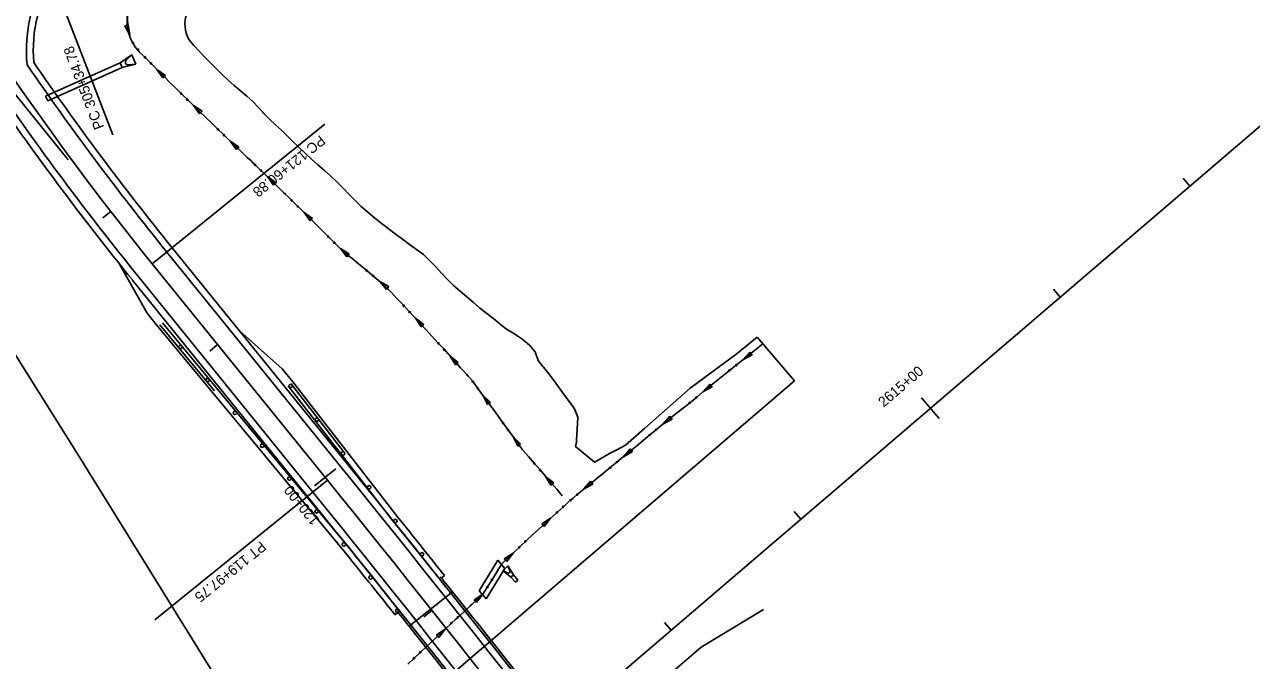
# Model space of a CAD drawing. Extents: x 916431 to 921570, y 1763982 to 1768032.
# Drawn here: x 918752 to 919470, y 1765157 to 1765530 of the extents above; entities that cross this region are included whole.
import ezdxf

# ---------------------------------------------------------------- set-up
doc = ezdxf.new("R2010")
doc.units = 0
for name, color, linetype in [('43', 7, 'Continuous'), ('B-Super-Deck', 7, 'Continuous'), ('R_Conc Ditch Paving', 7, 'Continuous'), ('R_Drainage', 7, 'Continuous'), ('R_Guardrail', 7, 'Continuous'), ('R_Horz Alg', 7, 'Continuous'), ('R_Horz Alg Annot', 7, 'Continuous'), ('R_Horz Alg Stationing', 7, 'Continuous'), ('R_Proposed Const Limits', 7, 'Continuous'), ('R_Proposed Road', 7, 'Continuous'), ('R_Shld', 7, 'Continuous'), ('R_Special Ditch', 7, 'Continuous')]:
    doc.layers.add(name, color=color, linetype=linetype)

# ---------------------------------------------------------------- blocks, each defined once
blk = doc.blocks.new('36F_PL')
at = {"layer": '43'}
for p, q in [((0, 0), (-0.15, -0.815)), ((0, 0), (0.3, 0)), ((0.45, -0.815), (0.3, 0)), ((-0.007, -0.402), (-0.15, -0.815)), ((0.308, -0.402), (0.45, -0.815)), ((-0.15, -0.815), (0.45, -0.815))]:
    blk.add_line(p, q, dxfattribs=at)
blk.add_arc((0.15, -0.456), 0.167, 19.04262, 160.95738, dxfattribs=at)
blk = doc.blocks.new('24F_PL')
at = {"layer": '43'}
for p, q in [((0, 0), (-0.1, -0.612)), ((0, 0), (0.2, 0)), ((0.2, 0), (0.3, -0.612)), ((-0.1, -0.612), (-0.011, -0.332)), ((-0.1, -0.612), (0.3, -0.612)), ((0.3, -0.612), (0.211, -0.332))]:
    blk.add_line(p, q, dxfattribs=at)
blk.add_arc((0.1, -0.367), 0.117, 17.52992, 162.47008, dxfattribs=at)

msp = doc.modelspace()

# ---------------------------------------------------------------- linework, layer by layer
at = {"layer": 'B-Super-Deck'}
for p, q in [((918995.36, 1765206.09), (918994.38, 1765205.31)), ((919002.21, 1765197.49), (918976.77, 1765177.26)), ((918969.92, 1765185.87), (918970.9, 1765186.65))]:
    msp.add_line(p, q, dxfattribs=at)
for radius, start, end in [(11474.16, 38.488592, 38.548508), (11475.41, 38.488592, 38.548507), (11474.16, 37.482766, 38.493585), (11475.41, 37.482766, 38.493585), (11442.91, 38.488593, 38.548678), (11444.16, 38.488593, 38.548677), (11442.91, 37.482752, 38.493599), (11444.16, 37.482752, 38.493599)]:
    msp.add_arc((910020.66, 1758054.88), radius, start, end, dxfattribs=at)
at = {"layer": 'R_Conc Ditch Paving'}
for p, q in [((919017.78, 1765198.07), (919028.8, 1765215.95)), ((919032.92, 1765211.18), (919028.8, 1765215.95)), ((919021.88, 1765193.28), (919032.92, 1765211.18)), ((919017.78, 1765198.07), (919021.88, 1765193.28))]:
    msp.add_line(p, q, dxfattribs=at)
at = {"layer": 'R_Drainage'}
for p, q in [((918807.55, 1765507.31), (918763.93, 1765487.87)), ((918808.77, 1765504.57), (918765.15, 1765485.13)), ((918763.93, 1765487.87), (918765.15, 1765485.13)), ((919036.4, 1765206.04), (919037.91, 1765207.35)), ((919036.4, 1765206.04), (919039.02, 1765203.02)), ((919037.91, 1765207.35), (919040.53, 1765204.32)), ((919039.02, 1765203.02), (919040.53, 1765204.32))]:
    msp.add_line(p, q, dxfattribs=at)
at = {"layer": 'R_Guardrail'}
for p, q in [((918862.8, 1765315.27), (918830.92, 1765353.79)), ((918944, 1765220.27), (918832.46, 1765355.07)), ((918967.37, 1765239.08), (918906.05, 1765318.17)), ((918938.27, 1765279.88), (918907.63, 1765319.4))]:
    msp.add_line(p, q, dxfattribs=at)
for points in [[(918970.66, 1765186.93), (918944, 1765220.27), (918832.46, 1765355.07)], [(918906.66, 1765317.38), (918967.37, 1765239.08), (918994.73, 1765204.87)]]:
    msp.add_lwpolyline(points, dxfattribs=at)
for centre in [(918842.94, 1765340.83), (918858.88, 1765321.57), (918907.45, 1765317.99), (918874.82, 1765302.31), (918922.77, 1765298.24), (918890.75, 1765283.05), (918938.09, 1765278.48), (918906.69, 1765263.79), (918953.41, 1765258.72), (918922.63, 1765244.53), (918968.73, 1765238.98), (918938.57, 1765225.27), (918984.34, 1765219.46), (918954.27, 1765205.83), (918969.88, 1765186.31)]:
    msp.add_circle(centre, 1, dxfattribs=at)
for radius, start, end in [(11474.16, 38.545676, 38.764426), (11444.16, 38.545526, 38.764276)]:
    msp.add_arc((910020.66, 1758054.88), radius, start, end, dxfattribs=at)
at = {"layer": 'R_Horz Alg'}
for p, q in [((918522.67, 1764654.46), (919661.81, 1765630.35)), ((918929, 1765262.78), (918826.39, 1765389.59))]:
    msp.add_line(p, q, dxfattribs=at)
for centre, radius, start, end in [((920196.91, 1766498.5), 1762.95, 202.25028, 218.97694), ((910020.66, 1758054.88), 11459.16, 34.999167, 38.976944)]:
    msp.add_arc(centre, radius, start, end, dxfattribs=at)
at = {"layer": 'R_Horz Alg Annot'}
msp.add_line((918663.37, 1765591.08), (918777.08, 1765450.54), dxfattribs=at)
for points in [[(918764.29, 1765566.55), (918803.28, 1765465.17)], [(918826.39, 1765389.59), (918927.45, 1765471.37)], [(918929, 1765262.78), (918827.94, 1765181.01)]]:
    msp.add_lwpolyline(points, dxfattribs=at)
at = {"layer": 'R_Horz Alg Stationing'}
for points in [[(919430.08, 1765439.73), (919433.98, 1765435.17)], [(918797.38, 1765416.61), (918802.13, 1765420.28)], [(919354.13, 1765374.67), (919358.04, 1765370.11)], [(918860.02, 1765338.49), (918864.69, 1765342.27)], [(919276.89, 1765311.13), (919287.3, 1765298.98)], [(918921.37, 1765259.49), (918933.81, 1765269.56)], [(919202.25, 1765244.55), (919206.15, 1765239.99)], [(918985.47, 1765182.79), (918990.16, 1765186.53)], [(919126.31, 1765179.49), (919130.21, 1765174.94)]]:
    msp.add_lwpolyline(points, dxfattribs=at)
at = {"layer": 'R_Proposed Const Limits'}
for points in [[(919074.23, 1765282.5), (919074.88, 1765285.18), (919074.93, 1765286.25), (919075.55, 1765299.36), (919075.57, 1765299.68), (919073.64, 1765304.62), (919070.66, 1765308.72), (919067.69, 1765312.82), (919064.71, 1765316.92), (919061.77, 1765321.05), (919058.73, 1765325.1), (919055.55, 1765329.03), (919055.19, 1765329.48), (919052.36, 1765332.96), (919050.67, 1765338.1), (919047.25, 1765341.85), (919043.59, 1765345.03), (919043.37, 1765345.22), (919040.51, 1765347.2), (919039.02, 1765348.21), (919036.5, 1765349.76), (919034.4, 1765350.95), (919030.31, 1765354.07), (919030.14, 1765354.22), (919026.37, 1765357.32), (919025.66, 1765357.87), (919022.31, 1765360.47), (919018.26, 1765363.62), (919014.43, 1765366.95), (919010.59, 1765370.28), (919006.75, 1765373.6), (919002.9, 1765376.92), (918999.29, 1765380.43), (918995.87, 1765384.09), (918992.45, 1765387.75), (918988.96, 1765391.37), (918985.38, 1765394.9), (918985.19, 1765395.07), (918981.22, 1765397.96), (918977.03, 1765401), (918972.85, 1765404.06), (918968.74, 1765407.17), (918964.62, 1765410.26), (918963.35, 1765411.2), (918960.47, 1765413.34), (918956.47, 1765416.53), (918952.65, 1765419.87), (918948.74, 1765423.14), (918945.17, 1765426.68), (918941.68, 1765430.29), (918938.21, 1765433.91), (918934.74, 1765437.54), (918931.04, 1765440.98), (918927.23, 1765444.32), (918923.35, 1765447.62), (918919.59, 1765451.01), (918915.86, 1765454.42), (918912.24, 1765457.92), (918908.81, 1765461.25), (918905.42, 1765464.55), (918903.95, 1765465.98), (918902.03, 1765467.84), (918898.6, 1765471.12), (918895.1, 1765474.34), (918891.79, 1765477.71), (918891.15, 1765478.45), (918888.69, 1765481.25), (918885.38, 1765484.64), (918881.75, 1765487.78), (918878.11, 1765490.91), (918874.46, 1765494.06), (918870.82, 1765497.21), (918867.41, 1765500.54), (918864.03, 1765503.9), (918860.64, 1765507.26), (918857.26, 1765510.63), (918853.97, 1765514.07), (918850.81, 1765517.61), (918847.82, 1765520.98)], [(918663.54, 1765493.36), (918697.72, 1765422.89), (918728.86, 1765363.64), (918783.6, 1765276.66), (918878.88, 1765122.86)], [(919180.63, 1765346.64), (919168.18, 1765336.52), (919154.83, 1765326.62), (919141.48, 1765316.71), (919128.21, 1765305.06), (919114.94, 1765293.41), (919103.47, 1765283.31)], [(919180.63, 1765346.64), (919202.49, 1765321.13)], [(919074.23, 1765282.5), (919085.37, 1765273.38), (919089.8, 1765275.9), (919094.26, 1765278.38), (919098.76, 1765280.82), (919103.47, 1765283.31)]]:
    msp.add_lwpolyline(points, dxfattribs=at)
msp.add_arc((918864.61, 1765529.99), 19.05, 112.67795, 208.20547, dxfattribs=at)
at = {"layer": 'R_Proposed Road'}
for p, q in [((918834.94, 1765396.51), (918937.55, 1765269.7)), ((918817.84, 1765382.68), (918920.45, 1765255.86))]:
    msp.add_line(p, q, dxfattribs=at)
for centre, radius, start, end in [((918837.71, 1765514.58), 85, 108.70584, 185.72161), ((920196.91, 1766498.5), 1751.95, 214.50329, 218.97694), ((920196.91, 1766498.5), 1773.95, 214.37448, 218.97694), ((910020.66, 1758054.88), 11470.16, 34.999167, 38.976944), ((910020.66, 1758054.88), 11448.16, 35.073221, 38.976944)]:
    msp.add_arc(centre, radius, start, end, dxfattribs=at)
at = {"layer": 'R_Shld'}
for p, q in [((918838.05, 1765399.03), (918940.66, 1765272.22)), ((918823.45, 1765360.64), (918806.94, 1765389.86)), ((918814.73, 1765380.16), (918917.34, 1765253.35)), ((918829.74, 1765352.87), (918824.04, 1765359.91)), ((918941.27, 1765218.08), (918829.74, 1765352.87)), ((918902.48, 1765328.15), (918877.45, 1765350.34)), ((918908.77, 1765320.37), (918902.48, 1765328.15)), ((919202.49, 1765321.13), (918784.8, 1764963.3)), ((918970.1, 1765241.27), (918908.77, 1765320.37)), ((918997.47, 1765207.05), (918995.71, 1765205.65)), ((919184.34, 1765187.07), (919147.89, 1765165.06)), ((918968.55, 1765183.97), (918970.31, 1765185.37)), ((919064.35, 1765093.5), (919147.89, 1765165.06))]:
    msp.add_line(p, q, dxfattribs=at)
for centre, radius, start, end in [((918837.71, 1765514.58), 81, 108.70584, 185.00335), ((920196.91, 1766498.5), 1747.95, 214.53735, 218.97694), ((920196.91, 1766498.5), 1777.95, 214.37448, 218.97694), ((920324.7, 1766574.12), 1930.36, 218.9491, 218.97694), ((910020.66, 1758054.88), 11474.16, 34.999167, 38.976944), ((910020.66, 1758054.88), 11444.16, 35.078536, 38.976944), ((910020.66, 1758054.88), 11477.66, 38.545676, 38.764426), ((910020.66, 1758054.88), 11440.66, 38.545526, 38.764276)]:
    msp.add_arc(centre, radius, start, end, dxfattribs=at)
at = {"layer": 'R_Special Ditch'}
for p, q in [((918812.31, 1765529.65), (918810.31, 1765528.96)), ((918810.31, 1765528.96), (918813.25, 1765523.63)), ((918813.25, 1765523.63), (918812.31, 1765529.65)), ((918829.16, 1765503.51), (918832.65, 1765498.52)), ((918834.15, 1765500.01), (918829.16, 1765503.51)), ((918832.65, 1765498.52), (918834.15, 1765500.01)), ((918850.5, 1765482.37), (918854.06, 1765477.43)), ((918855.54, 1765478.95), (918850.5, 1765482.37)), ((918854.06, 1765477.43), (918855.54, 1765478.95)), ((918872.1, 1765461.5), (918875.69, 1765456.58)), ((918877.16, 1765458.1), (918872.1, 1765461.5)), ((918875.69, 1765456.58), (918877.16, 1765458.1)), ((918893.79, 1765440.72), (918897.36, 1765435.78)), ((918898.84, 1765437.3), (918893.79, 1765440.72)), ((918897.36, 1765435.78), (918898.84, 1765437.3)), ((918915.26, 1765419.71), (918918.78, 1765414.74)), ((918920.27, 1765416.24), (918915.26, 1765419.71)), ((918918.78, 1765414.74), (918920.27, 1765416.24)), ((918936.58, 1765398.55), (918940.37, 1765393.79)), ((918941.77, 1765395.37), (918936.58, 1765398.55)), ((918940.37, 1765393.79), (918941.77, 1765395.37)), ((918959.61, 1765379.27), (918963.52, 1765374.6)), ((918964.88, 1765376.22), (918959.61, 1765379.27)), ((918963.52, 1765374.6), (918964.88, 1765376.22)), ((918980.52, 1765357.75), (918983.82, 1765352.62)), ((918985.37, 1765354.06), (918980.52, 1765357.75)), ((918983.82, 1765352.62), (918985.37, 1765354.06)), ((919176.3, 1765337.92), (919172.29, 1765333.33)), ((919177.62, 1765336.27), (919176.3, 1765337.92)), ((919000.8, 1765335.59), (919004.04, 1765330.43)), ((919005.61, 1765331.85), (919000.8, 1765335.59)), ((919004.04, 1765330.43), (919005.61, 1765331.85)), ((919172.29, 1765333.33), (919177.62, 1765336.27)), ((919152.86, 1765319.12), (919148.88, 1765314.51)), ((919148.88, 1765314.51), (919154.2, 1765317.48)), ((919154.2, 1765317.48), (919152.86, 1765319.12)), ((919020.05, 1765312.57), (919022.74, 1765307.1)), ((919024.45, 1765308.35), (919020.05, 1765312.57)), ((919022.74, 1765307.1), (919024.45, 1765308.35)), ((919129.46, 1765300.31), (919125.44, 1765295.73)), ((919125.44, 1765295.73), (919130.78, 1765298.65)), ((919130.78, 1765298.65), (919129.46, 1765300.31)), ((919037.72, 1765288.28), (919040.4, 1765282.81)), ((919042.11, 1765284.05), (919037.72, 1765288.28)), ((919040.4, 1765282.81), (919042.11, 1765284.05)), ((919106.28, 1765281.19), (919102.3, 1765276.58)), ((919107.61, 1765279.55), (919106.28, 1765281.19)), ((919102.3, 1765276.58), (919107.61, 1765279.55)), ((919056.77, 1765265.08), (919059.87, 1765259.84)), ((919061.48, 1765261.22), (919056.77, 1765265.08)), ((919059.87, 1765259.84), (919061.48, 1765261.22)), ((919083.02, 1765262.18), (919079.03, 1765257.58)), ((919079.03, 1765257.58), (919084.36, 1765260.54)), ((919084.36, 1765260.54), (919083.02, 1765262.18)), ((919059.66, 1765240.5), (919054.51, 1765237.23)), ((919055.94, 1765235.67), (919059.66, 1765240.5)), ((919054.51, 1765237.23), (919055.94, 1765235.67)), ((919037.66, 1765220.04), (919032.57, 1765216.7)), ((919032.57, 1765216.7), (919034.02, 1765215.16)), ((919034.02, 1765215.16), (919037.66, 1765220.04)), ((919020.04, 1765195.99), (919014.9, 1765192.72)), ((919016.33, 1765191.16), (919020.04, 1765195.99)), ((919014.9, 1765192.72), (919016.33, 1765191.16)), ((918997.96, 1765175.63), (918992.86, 1765172.31)), ((918994.3, 1765170.76), (918997.96, 1765175.63)), ((918992.86, 1765172.31), (918994.3, 1765170.76))]:
    msp.add_line(p, q, dxfattribs=at)
for points in [[(918812.74, 1765538.29), (918811.82, 1765535.12), (918812.02, 1765527.25), (918813.25, 1765523.63)], [(919066.51, 1765253.67), (919063.24, 1765257.52), (919059.97, 1765261.36), (919059.54, 1765261.85), (919056.68, 1765265.19), (919053.39, 1765269.01), (919053.37, 1765269.03), (919050.08, 1765272.83), (919046.77, 1765276.64), (919043.45, 1765280.44), (919043.28, 1765280.63), (919040.46, 1765284.51), (919037.49, 1765288.59), (919034.5, 1765292.66), (919031.55, 1765296.76), (919028.59, 1765300.86), (919025.62, 1765304.94), (919025.29, 1765305.4), (919022.65, 1765309.02), (919019.67, 1765313.1), (919016.67, 1765317.17), (919013.85, 1765321), (919013.68, 1765321.23), (919011.48, 1765323.73), (919010.33, 1765325.01), (919008.47, 1765327.08), (919006.97, 1765328.76), (919003.62, 1765332.48), (919003.47, 1765332.64), (919000.26, 1765336.19), (918999.67, 1765336.84), (918996.89, 1765339.9), (918993.52, 1765343.6), (918990.14, 1765347.3), (918986.75, 1765350.99), (918983.36, 1765354.68), (918979.96, 1765358.36), (918976.55, 1765362.03), (918973.14, 1765365.7), (918969.72, 1765369.36), (918966.24, 1765372.98), (918962.75, 1765376.59), (918962.58, 1765376.77), (918958.87, 1765379.89), (918954.97, 1765383.16), (918951.05, 1765386.42), (918947.13, 1765389.68), (918943.2, 1765392.93), (918942, 1765393.92), (918939.26, 1765396.18), (918935.46, 1765399.53), (918931.92, 1765403.1), (918928.37, 1765406.66), (918924.82, 1765410.22), (918921.26, 1765413.77), (918917.69, 1765417.31), (918914.11, 1765420.85), (918910.53, 1765424.38), (918906.94, 1765427.91), (918903.34, 1765431.43), (918899.74, 1765434.94), (918896.13, 1765438.45), (918892.51, 1765441.96), (918889.01, 1765445.31), (918885.54, 1765448.63), (918884.03, 1765450.07), (918882.06, 1765451.95), (918878.58, 1765455.28), (918875.11, 1765458.61), (918871.63, 1765461.94), (918870.91, 1765462.64), (918868.15, 1765465.29), (918864.68, 1765468.63), (918861.21, 1765471.99), (918857.73, 1765475.35), (918854.26, 1765478.71), (918850.79, 1765482.09), (918847.33, 1765485.47), (918843.87, 1765488.86), (918840.42, 1765492.26), (918836.98, 1765495.68), (918833.55, 1765499.1), (918830.13, 1765502.54), (918826.72, 1765505.99), (918823.31, 1765509.45), (918822.71, 1765510.06), (918821.28, 1765511.54)], [(918839.77, 1765492.91), (918836.98, 1765495.68), (918833.55, 1765499.1), (918830.13, 1765502.54), (918829.17, 1765503.52)], [(918839.8, 1765492.88), (918839.77, 1765492.91)], [(918861.27, 1765471.93), (918861.21, 1765471.99), (918857.73, 1765475.35), (918854.26, 1765478.71), (918850.79, 1765482.09), (918850.5, 1765482.37)], [(918861.29, 1765471.9), (918861.27, 1765471.93)], [(918882.93, 1765451.12), (918882.06, 1765451.95), (918878.58, 1765455.28), (918875.11, 1765458.61), (918872.1, 1765461.5)], [(918882.96, 1765451.1), (918882.93, 1765451.12)], [(918904.54, 1765430.26), (918903.34, 1765431.43), (918899.74, 1765434.94), (918896.13, 1765438.45), (918893.79, 1765440.72)], [(918904.57, 1765430.23), (918904.54, 1765430.26)], [(918925.9, 1765409.14), (918924.82, 1765410.22), (918921.26, 1765413.77), (918917.69, 1765417.31), (918915.26, 1765419.71)], [(918925.93, 1765409.11), (918925.9, 1765409.14)], [(918948.06, 1765388.9), (918947.13, 1765389.68), (918943.2, 1765392.93), (918942, 1765393.92), (918939.26, 1765396.18), (918936.58, 1765398.55)], [(918948.09, 1765388.88), (918948.06, 1765388.9)], [(918970.28, 1765368.76), (918969.72, 1765369.36), (918966.24, 1765372.98), (918962.75, 1765376.59), (918962.58, 1765376.77), (918959.61, 1765379.27)], [(918970.31, 1765368.73), (918970.28, 1765368.76)], [(918990.68, 1765346.71), (918990.14, 1765347.3), (918986.75, 1765350.99), (918983.36, 1765354.68), (918980.52, 1765357.75)], [(918990.71, 1765346.68), (918990.68, 1765346.71)], [(919069.74, 1765249.7), (919071.44, 1765251.23), (919072.8, 1765252.37), (919073.4, 1765252.87), (919073.46, 1765252.92), (919075.27, 1765254.43), (919079.11, 1765257.64), (919082.99, 1765260.79), (919086.88, 1765263.94), (919090.76, 1765267.1), (919094.62, 1765270.28), (919098.48, 1765273.45), (919102.35, 1765276.62), (919106.23, 1765279.79), (919110.11, 1765282.94), (919113.95, 1765286.14), (919117.77, 1765289.36), (919121.6, 1765292.58), (919125.46, 1765295.75), (919129.37, 1765298.88), (919133.3, 1765301.98), (919137.23, 1765305.07), (919141.15, 1765308.18), (919145.04, 1765311.34), (919148.89, 1765314.52), (919152.77, 1765317.68), (919156.64, 1765320.84), (919160.51, 1765324.01), (919164.39, 1765327.17), (919168.36, 1765330.22), (919172.28, 1765333.33), (919176.18, 1765336.46), (919180.07, 1765339.61), (919183.95, 1765342.77)], [(919183.95, 1765342.77), (919180.07, 1765339.61), (919176.18, 1765336.46), (919172.29, 1765333.33)], [(919010.84, 1765324.44), (919010.33, 1765325.01), (919008.47, 1765327.08), (919006.97, 1765328.76), (919003.62, 1765332.48), (919003.47, 1765332.64), (919000.8, 1765335.59)], [(919010.87, 1765324.41), (919010.84, 1765324.44)], [(919160.5, 1765324), (919156.64, 1765320.84), (919152.77, 1765317.68), (919148.89, 1765314.52), (919148.88, 1765314.51)], [(919160.53, 1765324.02), (919160.51, 1765324.01), (919160.5, 1765324)], [(919028.89, 1765300.45), (919028.59, 1765300.86), (919025.62, 1765304.94), (919025.29, 1765305.4), (919022.65, 1765309.02), (919020.05, 1765312.57)], [(919137.2, 1765305.04), (919133.3, 1765301.98), (919129.37, 1765298.88), (919125.46, 1765295.75), (919125.44, 1765295.73)], [(919137.23, 1765305.07), (919137.2, 1765305.04)], [(919028.91, 1765300.41), (919028.89, 1765300.44)], [(919046.93, 1765276.45), (919046.77, 1765276.64), (919043.45, 1765280.44), (919043.28, 1765280.63), (919040.46, 1765284.51), (919037.72, 1765288.28)], [(919113.89, 1765286.09), (919110.11, 1765282.94), (919106.23, 1765279.79), (919102.35, 1765276.62), (919102.3, 1765276.58)], [(919113.92, 1765286.12), (919113.89, 1765286.09)], [(919046.96, 1765276.43), (919046.93, 1765276.45)], [(919090.68, 1765267.03), (919086.88, 1765263.94), (919082.99, 1765260.79), (919079.11, 1765257.64), (919079.03, 1765257.58)], [(919090.71, 1765267.06), (919090.68, 1765267.03)], [(919066.51, 1765253.67), (919063.24, 1765257.52), (919059.97, 1765261.36), (919059.54, 1765261.85), (919056.77, 1765265.08)], [(918976.07, 1765155.04), (918979.71, 1765158.47), (918983.36, 1765161.9), (918987.01, 1765165.33), (918990.65, 1765168.77), (918994.29, 1765172.2), (918997.95, 1765175.62), (919001.6, 1765179.04), (919003.96, 1765181.2), (919005.29, 1765182.42), (919008.98, 1765185.8), (919012.66, 1765189.18), (919013.82, 1765190.24), (919016.32, 1765192.59), (919020.01, 1765195.97), (919022.79, 1765200.41), (919025.57, 1765204.85), (919028.31, 1765209.34), (919029.34, 1765211.07), (919031.02, 1765213.83), (919031.03, 1765213.85), (919031.45, 1765214.23), (919034.7, 1765217.25), (919038.35, 1765220.69), (919041.99, 1765224.12), (919045.63, 1765227.55), (919049.27, 1765230.98), (919052.95, 1765234.38), (919056.65, 1765237.75), (919059.6, 1765240.45), (919060.34, 1765241.12), (919063.14, 1765243.67), (919064.04, 1765244.49), (919067.72, 1765247.88), (919069.74, 1765249.7)], [(919048.61, 1765230.35), (919049.27, 1765230.98), (919052.95, 1765234.38), (919056.65, 1765237.75), (919059.6, 1765240.45), (919059.66, 1765240.5)], [(919048.58, 1765230.33), (919048.61, 1765230.35)], [(919027.97, 1765208.78), (919028.31, 1765209.34), (919029.34, 1765211.07), (919031.02, 1765213.83), (919031.03, 1765213.85), (919031.45, 1765214.23), (919034.7, 1765217.25), (919037.66, 1765220.04)], [(919027.95, 1765208.74), (919027.97, 1765208.78)], [(919009.01, 1765185.83), (919012.66, 1765189.18), (919013.82, 1765190.24), (919016.32, 1765192.59), (919020.01, 1765195.97), (919020.03, 1765196)], [(919008.98, 1765185.8), (919009.01, 1765185.83)], [(918987.03, 1765165.36), (918990.65, 1765168.77), (918994.29, 1765172.2), (918997.95, 1765175.62), (918997.96, 1765175.63)], [(918987, 1765165.33), (918987.01, 1765165.33), (918987.03, 1765165.36)]]:
    msp.add_lwpolyline(points, dxfattribs=at)
for centre in [(918815.16, 1765519.05), (918818.13, 1765515.01), (918822.11, 1765510.63), (918825.62, 1765507.05), (918843.32, 1765489.35), (918846.89, 1765485.84), (918864.85, 1765468.41), (918868.46, 1765464.94), (918886.54, 1765447.63), (918890.16, 1765444.16), (918908.1, 1765426.71), (918911.67, 1765423.2), (918929.42, 1765405.56), (918932.96, 1765402.01), (918951.9, 1765385.67), (918955.75, 1765382.46), (918973.68, 1765365.06), (918977.1, 1765361.39), (918994.04, 1765342.97), (918997.41, 1765339.27), (919164.41, 1765327.15), (919168.39, 1765330.2), (919014.09, 1765320.61), (919017.06, 1765316.58), (919145.04, 1765311.3), (919141.15, 1765308.14), (919031.8, 1765296.35), (919034.73, 1765292.29), (919117.76, 1765289.3), (919121.59, 1765292.53), (919098.45, 1765273.38), (919050.2, 1765272.64), (919053.48, 1765268.85), (919094.58, 1765270.19), (919075.22, 1765254.34), (919067.02, 1765247.29), (919071.38, 1765251.12), (919063.33, 1765243.89), (919041.28, 1765223.5), (919044.93, 1765226.94), (919025.32, 1765204.51), (919022.66, 1765200.26), (919005.28, 1765182.46), (919001.59, 1765179.08), (918979.7, 1765158.51), (918983.35, 1765161.94)]:
    msp.add_circle(centre, 0.375, dxfattribs=at)
msp.add_arc((918837.55, 1765531.81), 25.94, 120.31472, 230.76638, dxfattribs=at)

# ---------------------------------------------------------------- block references
at = {"layer": 'R_Drainage'}
for name, p, xscale, yscale, rotation in [('36F_PL', (918808.77, 1765504.57), 9.999999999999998, 9.999999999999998, 114.01494262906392), ('24F_PL', (919037.91, 1765207.35), 10.000000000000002, 10, -139.13257479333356)]:
    msp.add_blockref(name, p, dxfattribs=dict(at, xscale=xscale, yscale=yscale, rotation=rotation))

# ---------------------------------------------------------------- texts
at = {"layer": 'R_Horz Alg Annot'}
for s, rotation, p in [('PC 305+34.78', 111.03833, (918798.33, 1765469.69)), ('PC 121+60.88', 218.97694, (918924.68, 1765465.26)), ('PT 119+97.75', 218.97694, (918889.97, 1765227.34))]:
    msp.add_text(s, height=6, rotation=rotation, dxfattribs=at).set_placement(p)
at = {"layer": 'R_Horz Alg Stationing'}
for s, rotation, p in [('2615+00', 40.58639, (919254.71, 1765305.29)), ('120+00', 128.97694, (918924.69, 1765239.49))]:
    msp.add_text(s, height=6, rotation=rotation, dxfattribs=at).set_placement(p)

doc.saveas('drawing.dxf')
